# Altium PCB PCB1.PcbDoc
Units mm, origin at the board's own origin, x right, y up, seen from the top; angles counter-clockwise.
Board outline 50.8 x 50.8 mm, 2 copper layers (Top Layer, Bottom Layer); 8 components, 5 nets, 22 pads, 0 vias.
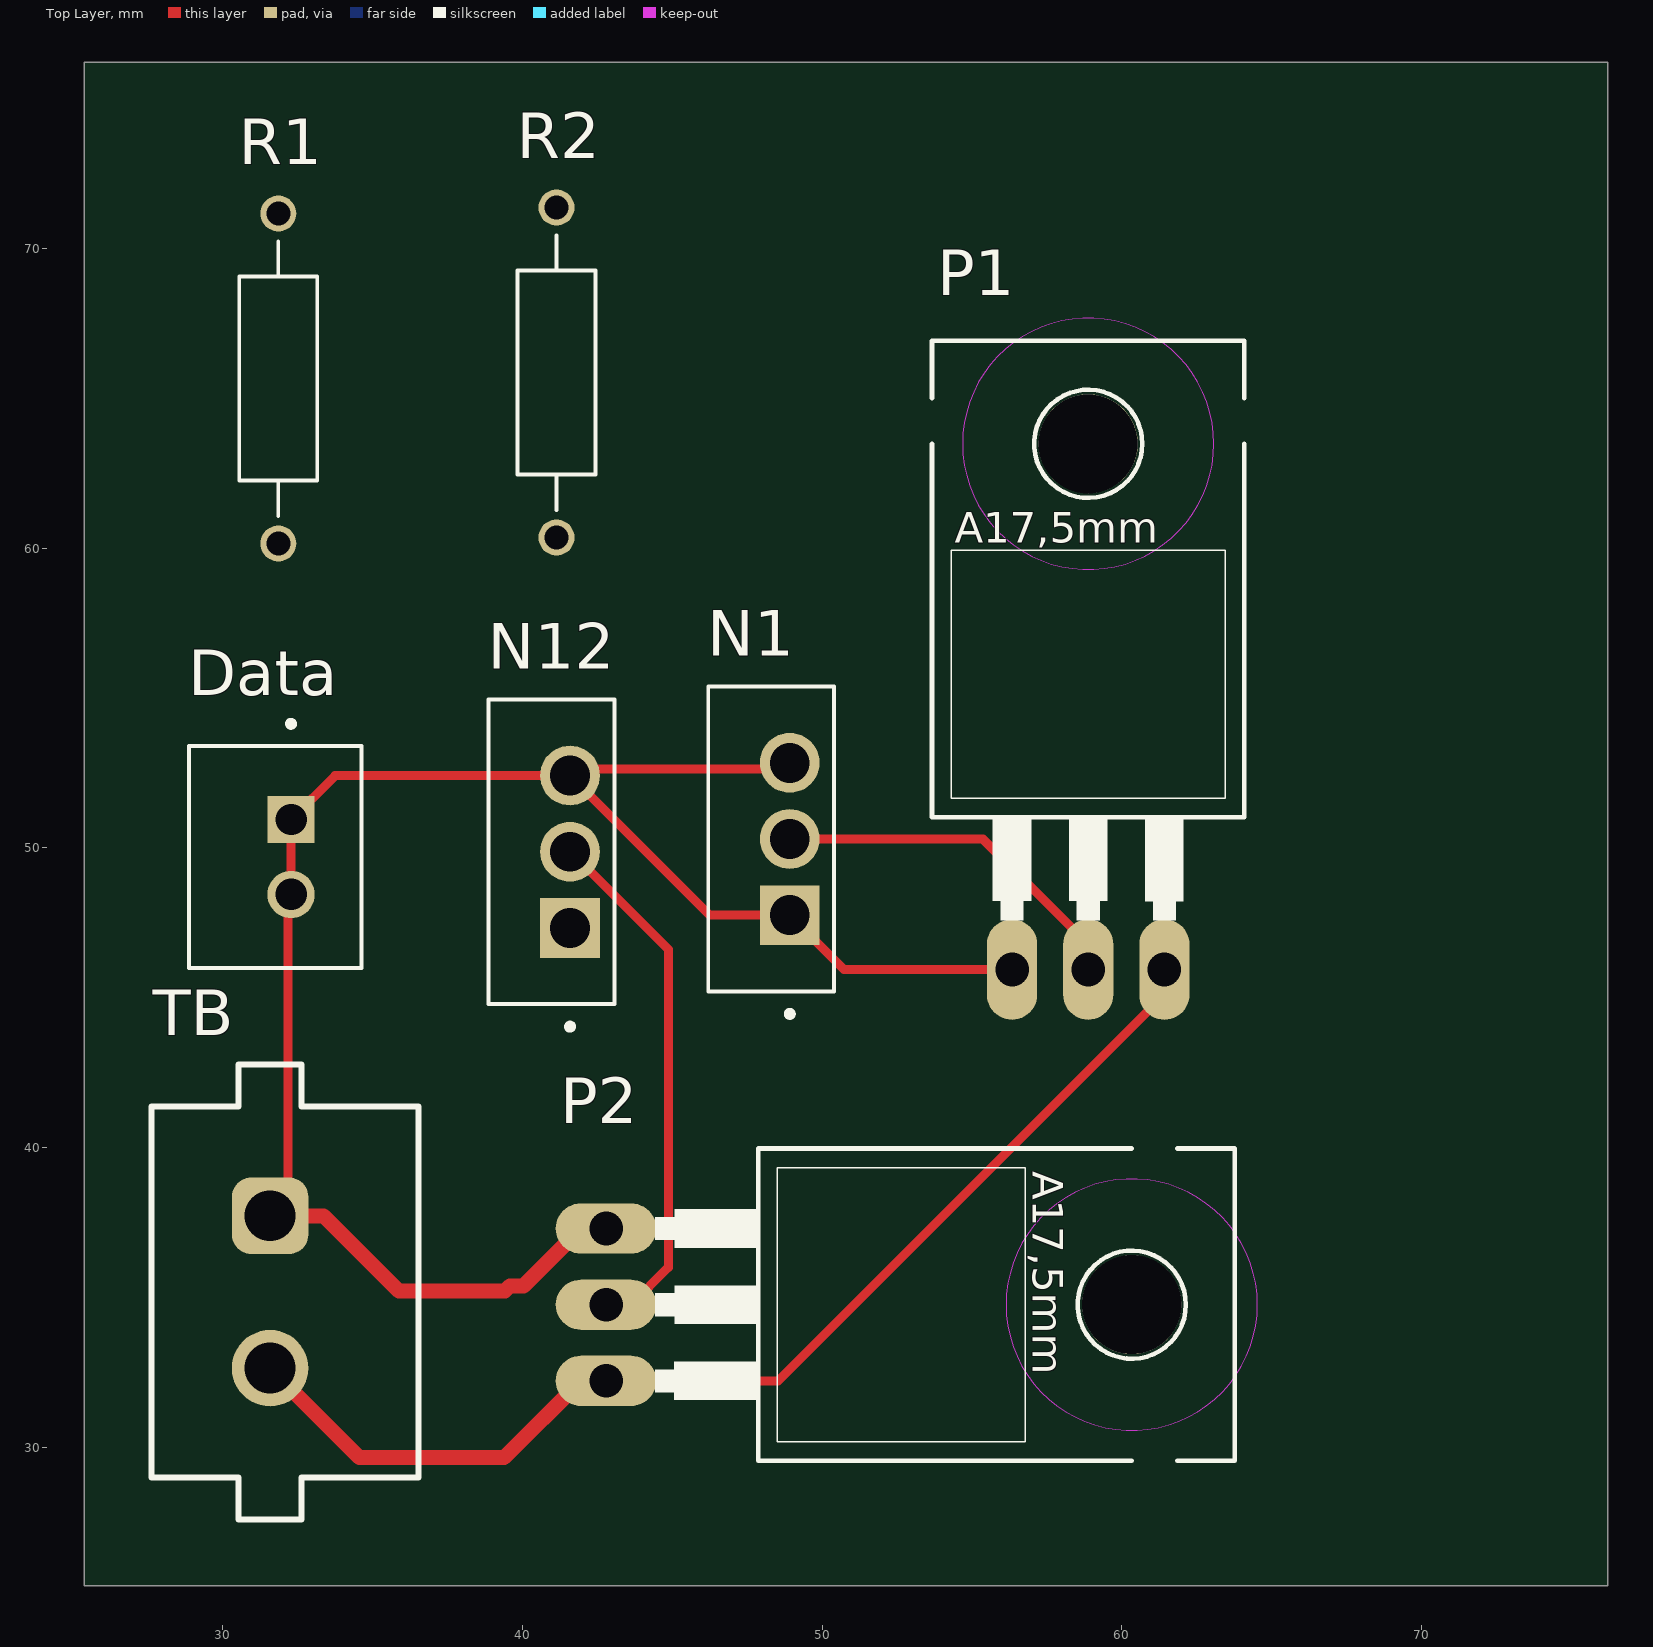
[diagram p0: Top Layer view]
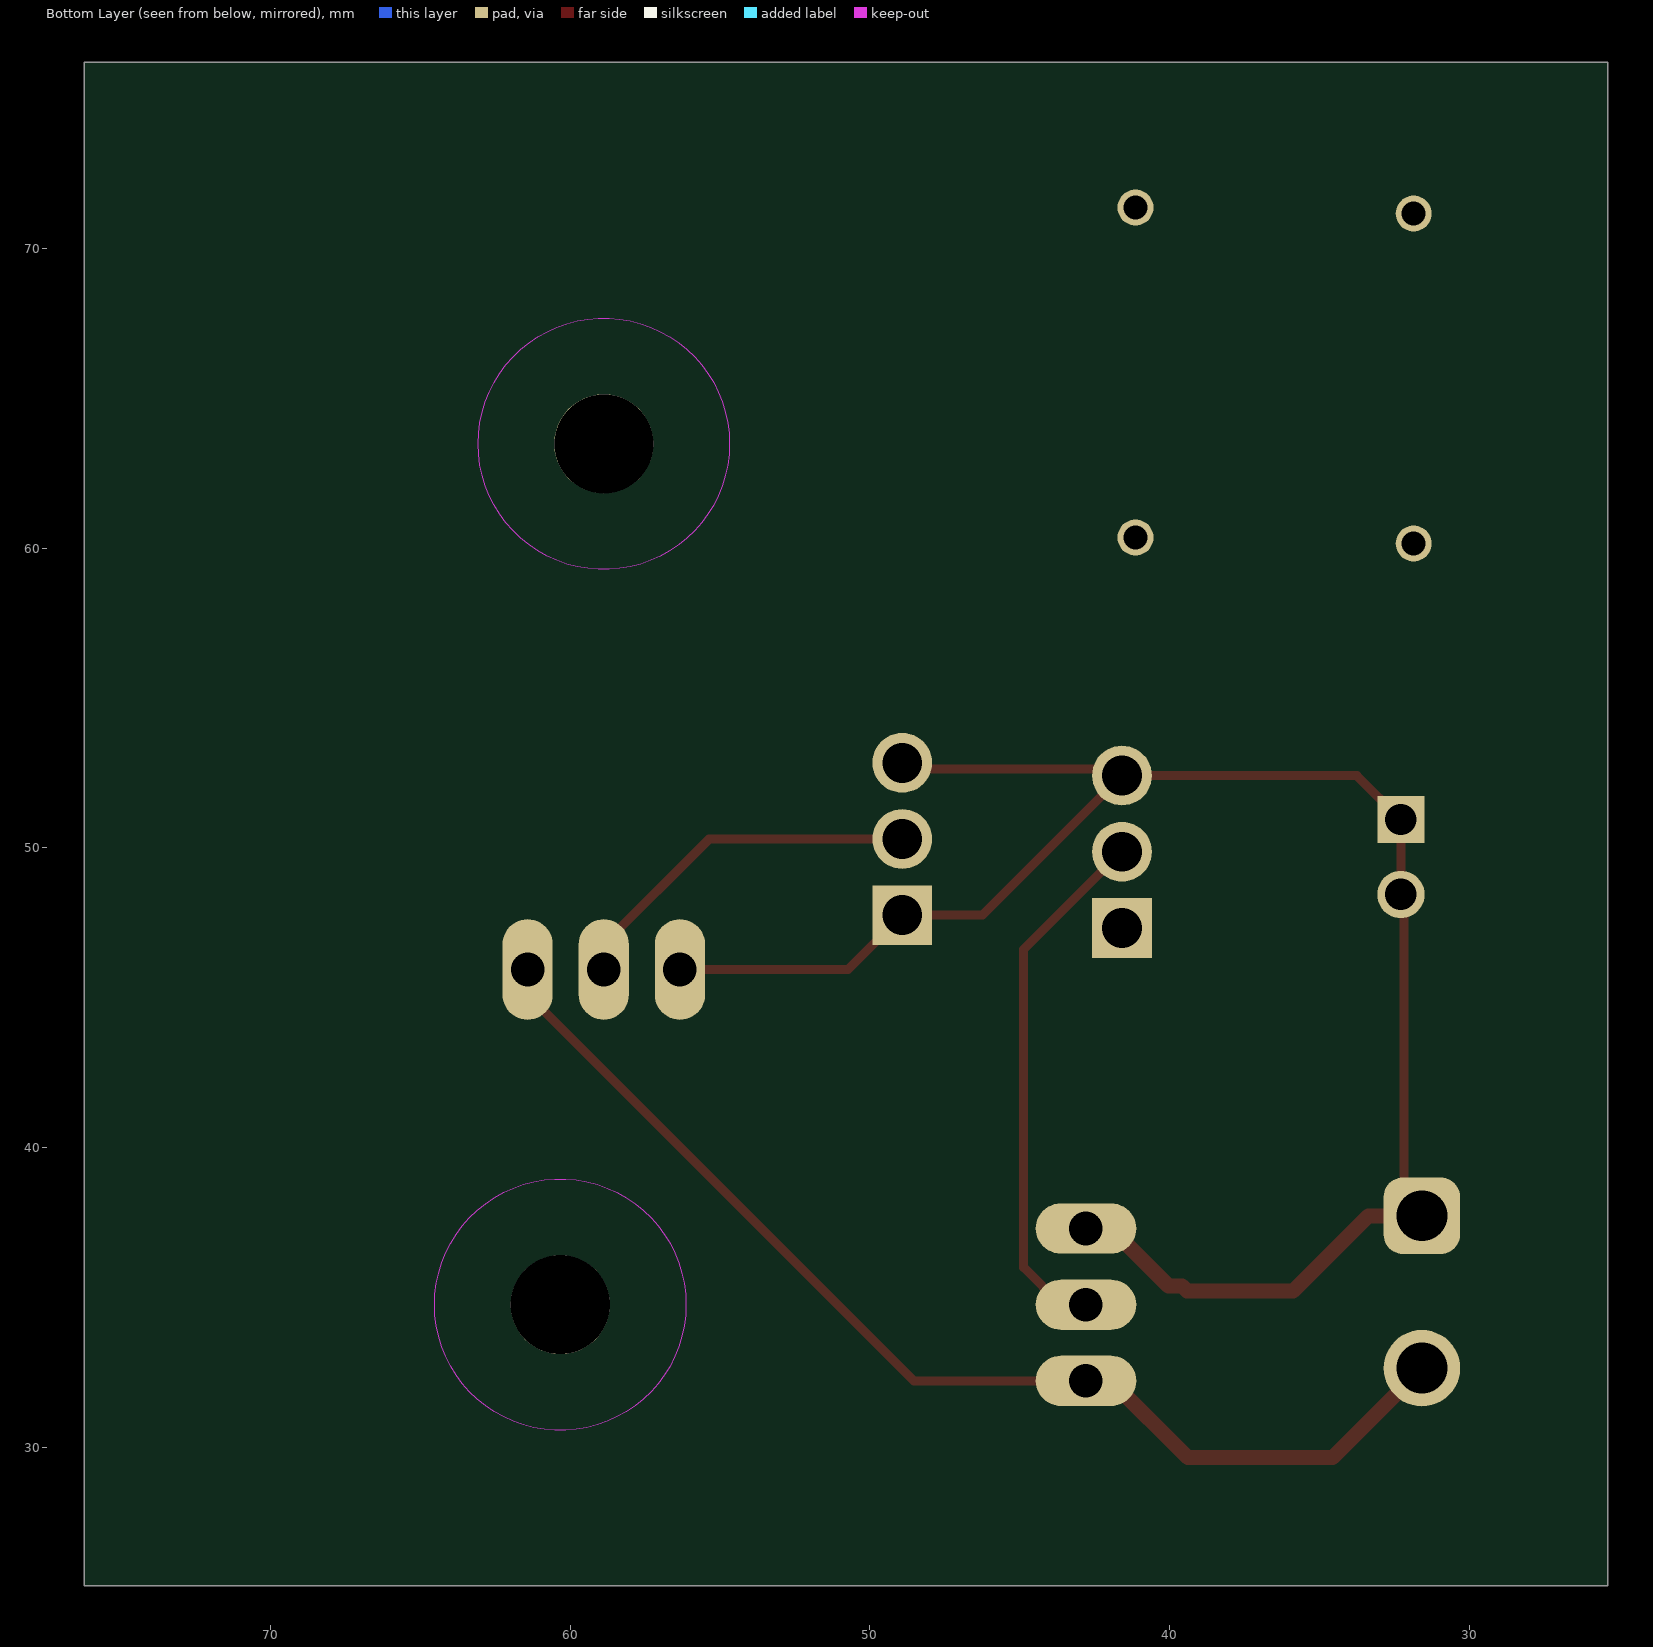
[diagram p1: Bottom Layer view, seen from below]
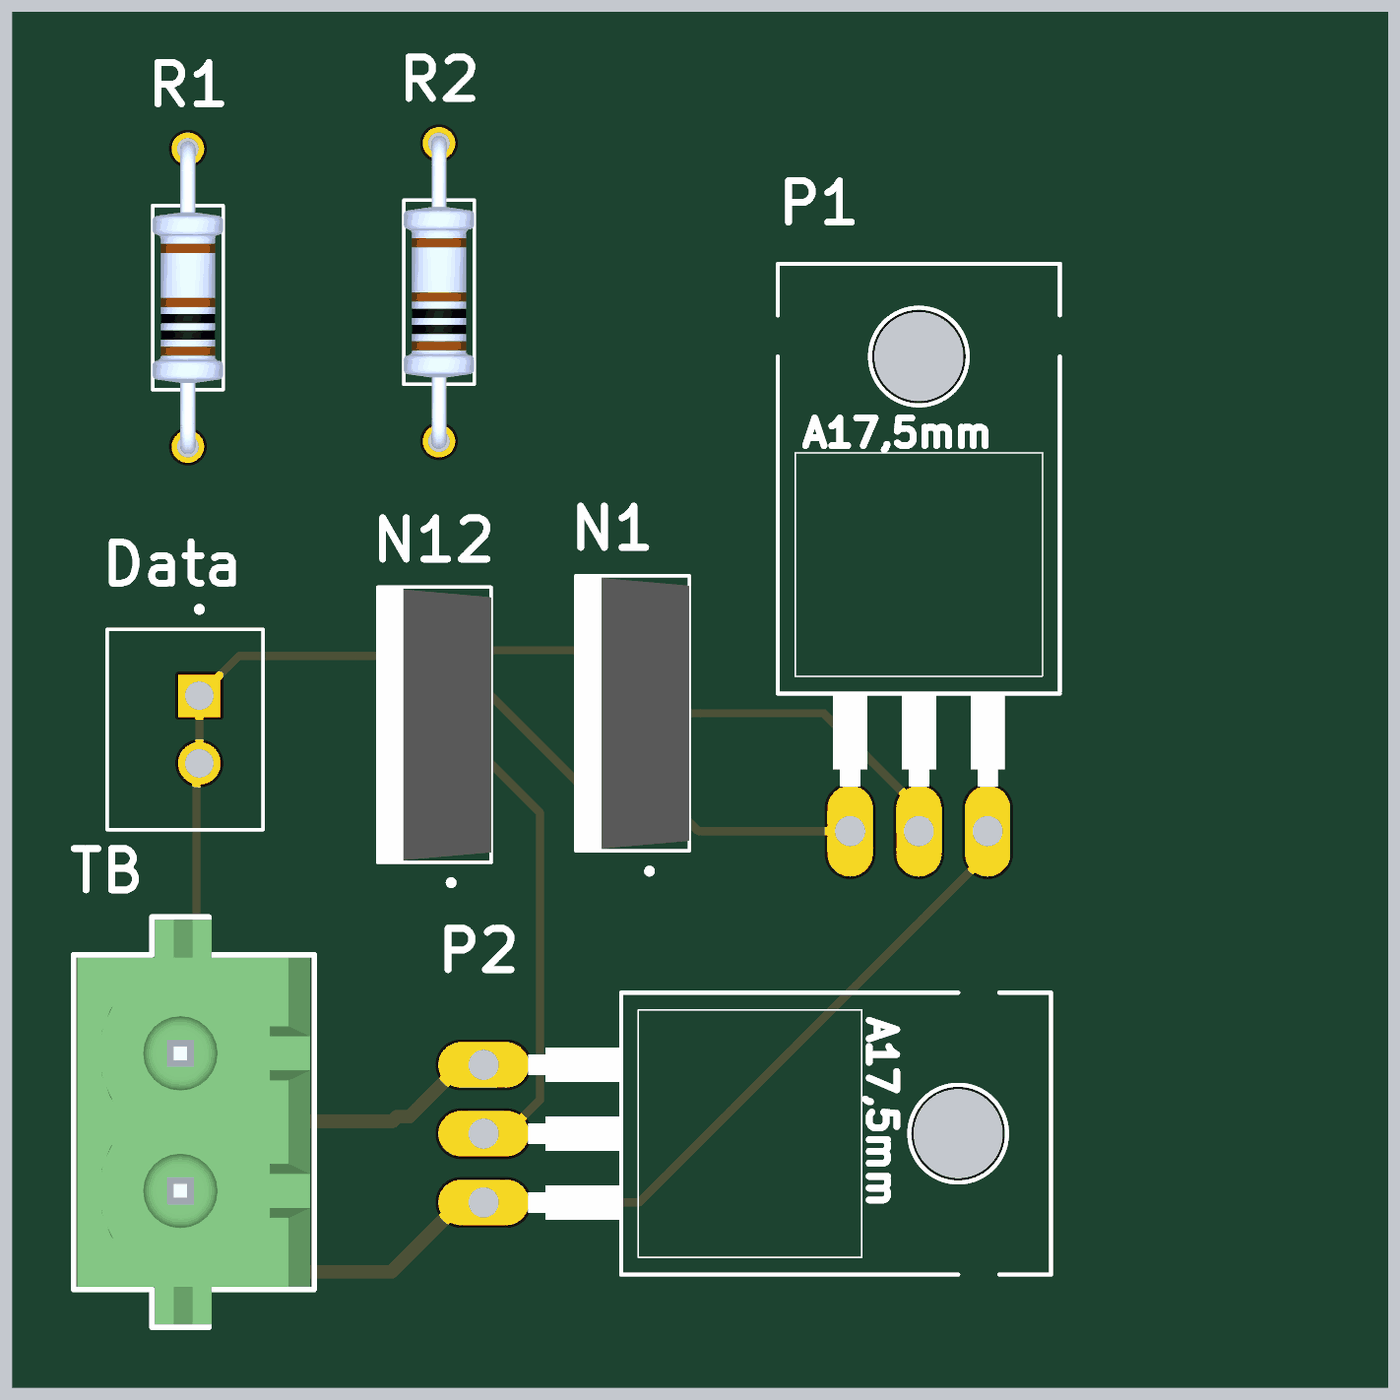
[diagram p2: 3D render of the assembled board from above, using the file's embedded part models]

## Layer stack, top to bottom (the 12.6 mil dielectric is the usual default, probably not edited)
Top Solder: solder mask 0.0102, Solder Resist, Dk 3.5
Top Layer: signal copper 0.0356
Dielectric 1: dielectric 0.32, FR-4, Dk 4.8
Bottom Layer: signal copper 0.0356
Bottom Solder: solder mask 0.0102, Solder Resist, Dk 3.5

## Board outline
25.4,25.4 76.2,25.4 76.2,76.2 25.4,76.2

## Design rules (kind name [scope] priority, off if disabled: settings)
Clearance [All] p1: gap=0.254 ignorepadtopadclearanceinfootprint=FALSE
HoleSize [All] p1: absolutevalues=TRUE maxlimit=6.3 minlimit=0.3 maxpercent=80.000 minpercent=20.000
MinimumAnnularRing [All] p1: minimumring=0.13
PolygonConnect [All] p1: connectstyle=Relief reliefconductorwidth=0.254 reliefentries=4 polygonreliefangle="90 Angle" airgapwidth=0.254
RoutingVias [All] p1: holewidth=0.711 width=1.27 viastyle="Through Hole" minholewidth=0.711 minwidth=1.27 maxholewidth=0.711 maxwidth=1.27
SolderMaskExpansion [All] p1: expansion=0.102 istentingtop=FALSE
SupplyNets "Schematic Supply Nets_1" [InNet('+12')] p1: voltage=0.000
SupplyNets "Schematic Supply Nets" [InNet('HighSignal')] p2: voltage=0.000
Width [All] p1: maxlimit=0.6 minlimit=0.254 preferedwidth=0.254 minimp=50.000000 maximp=50.000000 favimp=50.000000
29 further rules are at their usual default settings.

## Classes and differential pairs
component class Sheet1: Data M? N1 N12 P1 R1 TB

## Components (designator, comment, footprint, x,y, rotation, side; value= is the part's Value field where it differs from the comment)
Data "B2B-XH-A" JST_B2B-XH-A 31.775,49.7 r90 top
N1 "IRFZ44NPBF" TO254P1016X419X2286-3 48.925,50.3 r90 top
N12 "IRFZ44NPBF" TO254P1016X419X2286-3 41.6,49.875 r90 top
P1 "IRF4905" TO220BH 58.875,52.299 r0 top (schematic designator Q)
P2 "IRF4905" TO220BH 49.15,34.775 r270 top (schematic designator Q)
R1 "1000Ohm" RESAD1100W55L680D260 31.875,65.65 r90 top (schematic designator R*)
R2 "1000Ohm" RESAD1100W55L680D260 41.15,65.85 r90 top (schematic designator R*)
TB "691101710002" 691305530002 32.1,35.2 r270 top (schematic designator J?)

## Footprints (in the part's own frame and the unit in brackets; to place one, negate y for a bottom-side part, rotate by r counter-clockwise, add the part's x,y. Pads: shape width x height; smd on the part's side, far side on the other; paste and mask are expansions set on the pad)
691305530002 [mm] "5.08mm Vertical PCB Header with Plastic ears, 2p"
  rrect50% 2.55x2.55 hole 1.7: 1(-2.54,-0.5)
  round 2.55 hole 1.7: 2(2.54,-0.5)
  silkscreen extent -7.58,-4.45 7.58,4.45, body extent -7.48,-4.3 7.48,4.3, height 12.05
JST_B2B-XH-A [mm]
  rect 1.575x1.575 / inner round 1.575 / far side rect 1.575x1.575 hole 1.05: 1(1.25,-0.525)
  round 1.575 hole 1.05: 2(-1.25,-0.525)
  silkscreen extent -3.7,-2.88 4.54,2.88
RESAD1100W55L680D260 [mm]
  round 1.2 hole 0.8: 1(-5.5,0) 2(5.5,0)
  silkscreen extent -4.58,-1.3 4.58,1.3, body extent -5.77,-1.3 5.77,1.3, height 2.6
TO220BH [mil]
  oval 66x132 hole 44: D(0,-250) G(-100,-250) S(100,-250)
  round 130 hole 130 unplated: ""(0,440)
  Keep-Out Layer circle w0: c0,440 r165
  Keep-Out Layer circle w0: c0,440 r165
  silkscreen extent -205,-185 205,575
TO254P1016X419X2286-3 [mm]
  rect 1.995x1.995 / inner round 1.995 / far side rect 1.995x1.995 hole 1.33: 1(-2.54,0)
  round 1.995 hole 1.33: 2(0,0) 3(2.54,0)
  silkscreen extent -5.93,-1.48 5.08,2.72, body extent -5.08,-1.47 5.08,2.72, height 22.86

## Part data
Data: Package=None
N1 N12: "N-Channel 55 V 49A (Tc) 94W (Tc) Through Hole TO-220AB", Package="TO-220-3 Infineon"
P1 P2: "P-Channel 55V 74A _Tc_ 200W _Tc_ Through Hole TO-220AB", Package="TO-263-3 Infineon Technologies"
R1 R2: library part Component_1
TB: "WR-TBL Series 101 Horizontal Entry Modular, THT, pitch 5mm, 2p", Manufacturer="Wurth Elektronik", Operating Temperature Max=105°C, Operating Temperature Min=-40°C, Rated Current=16A, Working Voltage=250V

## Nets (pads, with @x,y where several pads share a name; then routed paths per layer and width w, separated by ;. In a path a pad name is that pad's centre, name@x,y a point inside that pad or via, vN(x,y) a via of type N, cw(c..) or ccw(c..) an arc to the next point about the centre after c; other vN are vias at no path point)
+12: P1.S P2.S TB.2 | length 38.3
  Top Layer w0.3: P2.S 48.539,32.235 61.415,45.111 P1.S
  Top Layer w0.5: TB.2 34.585,29.675 39.402,29.675 41.962,32.235 P2.S
HighSignal: Data.1 Data.2 N1.1 N1.3 N12.3 P1.G P2.G TB.1 | length 61.4
  Top Layer w0.3: TB.1 32.194,38.334 32.194,48.344 Data.2 Data.1 33.765,52.415 N12.3 ; N1.3 48.712,52.627 41.812,52.627 N12.3 ; P1.G 50.736,45.949 N1.1 46.255,47.76 N12.3
  Top Layer w0.5: TB.1 33.385,37.74 35.9,35.225 39.425,35.225 39.6,35.4 40.047,35.4 41.962,37.315 P2.G
NetM?_1: N12.2 P2.D | length 17.8
  Top Layer w0.3: N12.2 41.626,49.875 44.88,46.621 44.88,36.017 43.638,34.775 P2.D
NetM?_2: N1.2 P1.D | length 12.2
  Top Layer w0.3: N1.2 55.362,50.3 58.875,46.787 P1.D
NetN12_1: N12.1
pads on no net: P1. P2. R1.1 R1.2 R2.1 R2.2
